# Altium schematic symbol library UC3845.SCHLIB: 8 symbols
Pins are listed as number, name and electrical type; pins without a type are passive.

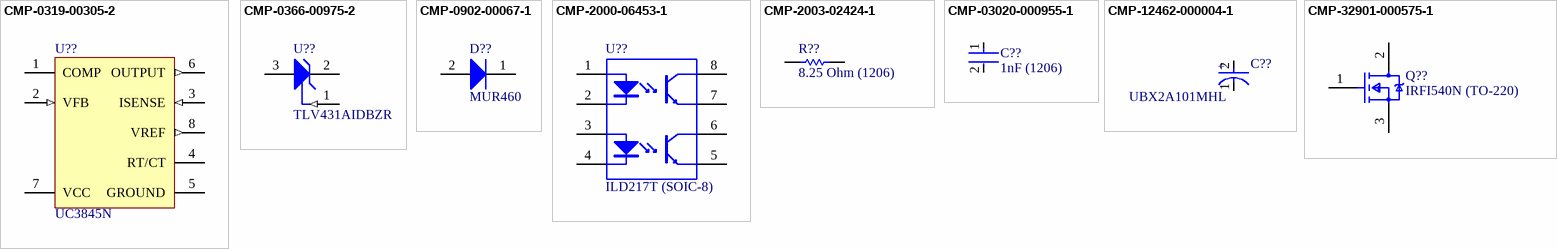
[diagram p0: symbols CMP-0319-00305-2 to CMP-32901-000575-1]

## CMP-0319-00305-2
designator U??, comment UC3845N
PWM Controller with Current Control, 50 % Duty Cycle, 0 to +70 degC, 8-pin PDIP (P), Green (RoHS & no Sb/Br); Manufacturer: Texas Instruments; Rating: Catalog; UVLO Thresholds On/Off(V): 8.4/7.6; Regulated Outputs(#): 1; Duty Cycle(Max)(%): 50; Frequency(Max)(kHz): 450; Topology: Boost, Buck, Flyback, Forward
footprint P0008A (DIP, 8-Leads, Body 10.15x6.6mm, Pitch 2.54mm)
pins: 1 COMP, 2 VFB (in), 3 ISENSE (in), 4 RT/CT, 5 GROUND (power), 6 OUTPUT (out), 7 VCC (power), 8 VREF (out)

## CMP-0366-00975-2
designator U??, comment TLV431AIDBZR
Low Voltage Adjustable Precision Shunt Regulator, 39 ppm / degC, 15 mA, -40 to 85 degC, 3-pin SOT-23 (DBZ), Green (RoHS & no Sb/Br); Manufacturer: Texas Instruments; Temp Coeff(Typ)(ppm/ degree C): 39; VO Adj(Max)(V): 6; SubFamily: Shunt Voltage Reference; Min Iz for Regulation(uA): 80; Temp Coeff(Max)(ppm/ degree C): 129; VO Adj(Min)(V): 1.24; Initial Accuracy @ 25/deg C(%): 1; Iout/Iz(Max)(mA): 15; Rating: Catalog
footprint DBZ0003A_N (SOT23, 3-Leads, Body 3.04x1.4mm, Pitch 0.95mm, IPC Medium Density)
footprint DBZ0003A_L (SOT23, 3-Leads, Body 3.04x1.4mm, Pitch 0.95mm, IPC High Density)
footprint DBZ0003A_M (SOT23, 3-Leads, Body 3.04x1.4mm, Pitch 0.95mm, IPC Low Density)
pins: 1 REF (in), 2 CATHODE, 3 ANODE

## CMP-0902-00067-1
designator D??, comment MUR460
SWITCHMODE(TM) Power Rectifier, 2-Pin Axial_Lead, Pb-Free, Bulk Bag; Manufacturer: On Semiconductor; IFSM Max (A): 110; Type: Ultrafast; VRRM Max (V): 600
footprint ONSC-AXIAL_LEAD-2-267-05_V (AXIAL, 2-Leads, Diameter 5.05mm)
pins: 1 K, 2 A

## CMP-2000-06453-1
designator U??, comment ILD217T (SOIC-8)
Optocoupler, Phototransistor Output, Dual Channel, 4000 VRMS, -55 to 100 degC, 8-Pin SOIC, RoHS, Tape and Reel; Manufacturer: Vishay; Manufacturer: Vishay Semiconductors; Manufacturer Part Number: ILD207T; Voltage - Output (Max): 70V; Vce Saturation (Max): 400mV; Number of Channels: 2; Voltage - Forward (Vf) (Typ): 1.2V; EDA / CAD Models: DownloadfromAcceleratedDesigns; Current Transfer Ratio (Min): 100%@10mA; Current Transfer Ratio (Max): 200%@10mA; Input Type: DC; Current - DC Forward (If) (Max): 30mA; Rise / Fall Time (Typ): 3µs,4.7µs; Turn On / Turn Off Time (Typ): 6µs,5µs; Catalog Drawings: OptocouplerCircuit; Other Names: 751-1310-1ILD207TGICTILD207TGICT-ND; Online Catalog: ILD205T,206T,207T,211T,213T,217TSeries
footprint VISH-SOIC-8_C_V (SOIC, 8-Leads, Body 6x4mm, Pitch 1.27mm)
pins: 1 A, 2 K, 3 A, 4 K, 5 E, 6 C, 7 E, 8 C

## CMP-2003-02424-1
designator R??, comment 8.25 Ohm (1206)
Manufacturer: Vishay Dale; Part Number: CRCW12068R25FKEA
footprint RESC3216X60X45NL10T20 (Chip Resistor, 2-Leads, Body 3.20x1.60mm, IPC Medium Density)
footprint RESC3216X60X45LL10T20 (Chip Resistor, 2-Leads, Body 3.20x1.60mm, IPC High Density)
footprint RESC3216X60X45ML10T20 (Chip Resistor, 2-Leads, Body 3.20x1.60mm, IPC Low Density)
pins: 1, 2
1 alternate drawing of the same symbol

## CMP-03020-000955-1
designator C??, comment 1nF (1206)
Multilayer Ceramic Capacitor, C Series, 1000 Pf, - 5%, C0g / Np0, 100 V, 1206 [3216 Metric] Rohs Compliant: Yes; Manufacturer: KEMET; Manufacturer Part Number: C1206C102J1GACTU; Capacitance: 1,000 pF; Voltage Rating: 100 V; Tolerance: 0.05; Automotive Grade: Grade 0; Temperature Coefficient: 15%; Value: 1,000 pF
footprint FP-C1206C-EB-MFG
footprint FP-C1206C-EB-IPC_C
footprint FP-C1206C-EB-IPC_B
footprint FP-C1206C-EB-IPC_A
pins: 1, 2

## CMP-12462-000004-1
designator C??, comment UBX2A101MHL
CAP ALUM 100UF 20% 100V RADIAL; Manufacturer: Nichicon; Material: Aluminum; Automotive Grade: Grade 0; Ripple Current: 950mA; Leakage Current: 300uA; Life: 1000Hours; Dissipation Factor: 8%
footprint FP-UBX2A101MHL-MFG
pins: 1 C, 2 A

## CMP-32901-000575-1
designator Q??, comment IRFI540N (TO-220)
MOSFET N-CH 100V 20A TO220FP; Manufacturer: Infineon; Manufacturer Part Number: IRFI540NPBF; Gate to Source Voltage (Vgs): 20V; Power Dissipation: 54W; Rds On Max: 52mR; Threshold Voltage: 4V; Turn-On Delay Time: 8.2ns; Turn-Off Delay Time: 44ns; Input Capacitance: 1.4nF; Element Configuration: Single
footprint FP-PG-TO220-3-MFG
pins: 1 G, 2 D, 3 S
